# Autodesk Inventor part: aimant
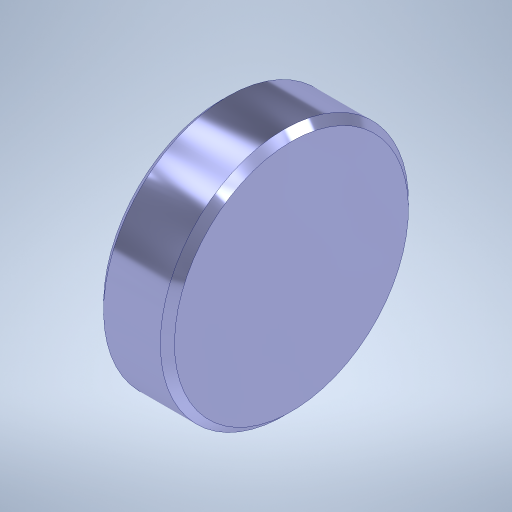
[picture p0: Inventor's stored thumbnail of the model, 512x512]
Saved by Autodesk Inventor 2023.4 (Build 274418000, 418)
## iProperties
Created: 2024-03
Part Number: aimant
Material: Acier
Document SubType Name: Modeling
Designer: mel
Density: 7.85 g/cm^3
Appearance: Chrome - Bleu poli
Author: mel
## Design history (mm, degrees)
sketch "Esquisse1"
  geometry: L1 (0, 0)-(1, 0); L2 (1, 0)-(1, 1.75); L3 (1, 1.75)-(0, 1.75); L4 (0, 1.75)-(0, 0)
  constraints: 8 end point, 2 parallel, 1 horizontal, 1 perpendicular
  dimensions: "d0" = 1 distance of L3.end L2.end; "d1" = 1.75 distance of L2.end L1.end
revolve "Révolution1" sketch "Esquisse1" stored, may be unused: angle "d2" = 90 deg
chamfer "Chanfrein1" distance "d3" = 0.1; stored, may be unused: second distance "d4" = 2, angle "d5" = 45 deg
node "Solide1"
